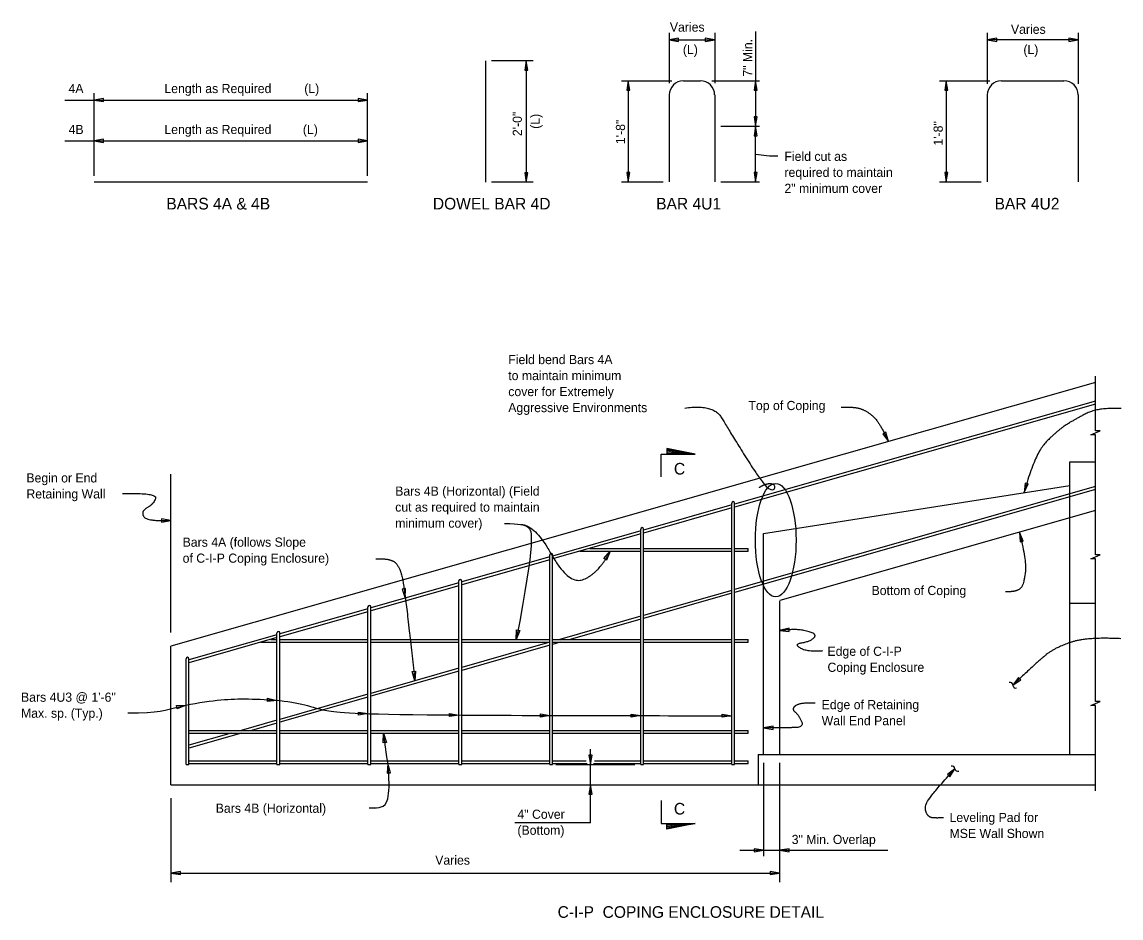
# Model space of a CAD drawing. Extents: x -15.2 to 30.6, y 0.3 to 20.9.
# Drawn here: x 0.43 to 18.56, y 0.33 to 15.1 of the extents above; entities that cross this region are included whole.
import ezdxf

# ---------------------------------------------------------------- set-up
doc = ezdxf.new("R2010")
doc.units = 0
for name, color, linetype in [('Dimension', 7, 'Continuous'), ('Rebar', 7, 'Continuous'), ('Rebar_h', 7, 'Continuous'), ('TextStructures', 7, 'Continuous'), ('WallConc', 7, 'Continuous'), ('WallConc_h', 7, 'Continuous')]:
    doc.layers.add(name, color=color, linetype=linetype)

msp = doc.modelspace()

# ---------------------------------------------------------------- linework, layer by layer
at = {"layer": 'Dimension'}
for p, q in [((11.103, 14.92), (11.103, 14.095)), ((11.854, 14.92), (11.854, 14.095)), ((12.529, 14.945), (12.529, 14.132)), ((16.349, 14.92), (16.349, 14.084)), ((17.849, 14.92), (17.849, 14.084)), ((17.849, 14.807), (16.349, 14.807)), ((8.859, 14.461), (8.171, 14.461)), ((8.746, 14.461), (8.746, 12.461)), ((10.316, 14.132), (11.144, 14.132)), ((10.429, 14.132), (10.429, 12.465)), ((11.805, 14.132), (12.594, 14.132)), ((12.529, 14.132), (12.529, 13.382)), ((15.562, 14.132), (16.394, 14.132)), ((15.674, 14.132), (15.674, 12.465)), ((1.136, 13.815), (6.128, 13.815)), ((1.619, 12.565), (1.619, 13.928)), ((6.128, 12.565), (6.128, 13.928)), ((11.954, 13.382), (12.594, 13.382)), ((12.529, 12.465), (12.529, 13.382)), ((1.136, 13.14), (6.128, 13.14)), ((8.859, 12.461), (8.171, 12.461)), ((10.316, 12.465), (11.004, 12.465)), ((11.954, 12.465), (12.594, 12.465)), ((15.562, 12.465), (16.249, 12.465)), ((11.532, 7.976), (11.063, 8.058)), ((11.063, 8.048), (11.532, 7.976)), ((11.532, 7.976), (11.063, 8.036)), ((11.063, 8.022), (11.532, 7.976)), ((11.532, 7.976), (11.063, 8.008)), ((11.063, 7.993), (11.532, 7.976)), ((2.884, 5.034), (2.884, 7.648)), ((9.805, 1.898), (9.805, 3.113)), ((9.235, 2.856), (10.536, 2.856)), ((12.661, 2.886), (12.661, 1.345)), ((12.925, 2.886), (12.925, 0.92)), ((2.885, 2.302), (2.885, 0.92)), ((9.805, 1.898), (8.559, 1.898)), ((11.063, 1.871), (11.532, 1.888)), ((11.532, 1.888), (11.063, 1.856)), ((11.063, 1.842), (11.532, 1.888)), ((11.532, 1.888), (11.063, 1.828)), ((11.063, 1.816), (11.532, 1.888)), ((11.532, 1.888), (11.063, 1.806)), ((12.271, 1.443), (14.709, 1.443)), ((2.885, 1.068), (12.925, 1.068))]:
    msp.add_line(p, q, dxfattribs=at)
for points in [[(11.102, 14.807), (11.259, 14.781), (11.259, 14.834)], [(11.854, 14.807), (11.697, 14.834), (11.697, 14.781)], [(16.349, 14.807), (16.505, 14.781), (16.505, 14.834)], [(17.849, 14.807), (17.693, 14.834), (17.693, 14.781)], [(8.746, 14.461), (8.72, 14.305), (8.773, 14.305)], [(10.428, 14.132), (10.402, 13.976), (10.455, 13.976)], [(12.529, 14.132), (12.502, 13.976), (12.555, 13.976)], [(15.674, 14.132), (15.648, 13.976), (15.701, 13.976)], [(1.619, 13.815), (1.775, 13.789), (1.775, 13.842)], [(6.128, 13.815), (5.972, 13.842), (5.972, 13.789)], [(12.529, 13.382), (12.555, 13.538), (12.502, 13.538)], [(12.529, 13.382), (12.502, 13.226), (12.555, 13.226)], [(1.619, 13.14), (1.775, 13.114), (1.775, 13.167)], [(6.128, 13.14), (5.972, 13.167), (5.972, 13.114)], [(8.746, 12.461), (8.773, 12.617), (8.72, 12.617)], [(10.429, 12.465), (10.455, 12.622), (10.402, 12.622)], [(12.529, 12.465), (12.555, 12.622), (12.502, 12.622)], [(15.674, 12.465), (15.701, 12.622), (15.648, 12.622)], [(14.721, 8.184), (14.675, 8.336), (14.628, 8.313)], [(16.958, 7.341), (17.026, 7.484), (16.975, 7.498)], [(2.884, 6.884), (2.728, 6.908), (2.729, 6.855)], [(16.881, 6.688), (16.891, 6.53), (16.942, 6.542)], [(10.026, 6.256), (10.131, 6.374), (10.071, 6.228)], [(6.75, 5.602), (6.753, 5.76), (6.7, 5.752)], [(8.637, 5.069), (8.581, 4.921), (8.585, 5.08)], [(12.925, 5.07), (13.083, 5.051), (13.08, 5.104)], [(6.918, 4.397), (6.908, 4.239), (6.865, 4.391)], [(16.772, 4.165), (16.902, 4.255), (16.865, 4.293)], [(2.976, 3.829), (3.134, 3.837), (2.988, 3.777)], [(4.48, 3.952), (4.634, 3.916), (4.477, 3.899)], [(5.978, 3.723), (6.134, 3.697), (5.978, 3.67)], [(7.478, 3.701), (7.634, 3.674), (7.478, 3.648)], [(8.978, 3.693), (9.134, 3.667), (8.978, 3.641)], [(10.478, 3.69), (10.634, 3.664), (10.478, 3.637)], [(11.978, 3.689), (12.134, 3.663), (11.978, 3.637)], [(12.661, 3.463), (12.817, 3.436), (12.817, 3.489)], [(6.388, 3.216), (6.392, 3.374), (6.44, 3.223)], [(9.805, 2.856), (9.831, 3.012), (9.778, 3.012)], [(6.462, 2.874), (6.452, 2.716), (6.505, 2.722)], [(15.817, 2.789), (15.692, 2.691), (15.732, 2.656)], [(9.805, 2.523), (9.778, 2.367), (9.831, 2.367)], [(12.661, 1.443), (12.505, 1.469), (12.505, 1.416)], [(12.925, 1.443), (13.082, 1.416), (13.082, 1.469)], [(2.885, 1.068), (3.041, 1.042), (3.041, 1.095)], [(12.925, 1.068), (12.769, 1.095), (12.769, 1.042)]]:
    msp.add_lwpolyline(points, close=True, dxfattribs=at)
for points in [[(11.103, 14.807), (11.854, 14.807)], [(18.137, 7.046), (18.137, 8.293), (18.059, 8.293), (18.137, 8.326), (18.214, 8.36), (18.137, 8.36), (18.137, 9.259)], [(10.969, 7.601), (10.969, 7.976), (11.532, 7.976), (11.063, 8.07), (11.063, 7.976)], [(18.137, 5.519), (18.137, 6.251), (18.059, 6.251), (18.137, 6.285), (18.214, 6.318), (18.137, 6.318), (18.137, 7.046)], [(18.136, 2.423), (18.136, 3.83), (18.059, 3.83), (18.136, 3.864), (18.214, 3.898), (18.136, 3.898), (18.136, 5.519)], [(10.969, 2.263), (10.969, 1.888), (11.532, 1.888), (11.063, 1.794), (11.063, 1.888)]]:
    msp.add_lwpolyline(points, dxfattribs=at)
for centre, radius, start, end in [((12.864, 14.772), 1.878, 259.7182, 270.8702), ((16.727, 4.166), 0.0447, 358.2978, 110.025), ((16.817, 4.163), 0.0447, 178.2978, 290.025), ((15.772, 2.788), 0.0447, 1.9589, 113.6861), ((15.861, 2.791), 0.0447, 181.9589, 293.6861)]:
    msp.add_arc(centre, radius, start, end, dxfattribs=at)
for points, degree in [([(11.359, 8.735), (11.83, 8.806), (12.101, 8.349), (12.68, 7.426), (12.846, 7.371), (12.846, 7.486), (12.689, 7.486), (12.586, 7.422)], 2), ([(13.942, 8.75), (14.165, 8.761), (14.38, 8.678), (14.572, 8.502), (14.721, 8.184)], 2), ([(18.556, 8.729), (18.182, 8.743), (17.808, 8.558), (17.521, 8.378), (17.129, 7.985), (16.958, 7.341)], 2), ([(2.086, 7.325), (2.652, 7.342), (2.61, 7.16), (2.384, 7.03), (2.486, 6.865), (2.884, 6.884)], 2), ([(8.385, 6.833), (8.64, 6.823), (8.78, 6.823), (8.904, 6.607), (8.581, 4.921)], 3), ([(8.659, 6.816), (8.891, 6.808), (9.45, 5.808), (9.944, 6.017), (10.131, 6.374)], 2), ([(16.881, 6.688), (17.005, 6.189), (16.949, 5.843), (16.893, 5.745), (16.76, 5.702), (16.651, 5.708)], 2), ([(6.263, 6.248), (6.525, 6.265), (6.681, 6.073), (6.748, 5.65), (6.857, 4.723), (6.908, 4.239)], 2), ([(13.633, 4.73), (13.376, 4.708), (13.156, 4.846), (13.43, 4.887), (13.552, 5.01), (13.254, 5.09), (13.009, 5.075), (12.925, 5.07)], 2), ([(18.551, 4.932), (18.004, 4.96), (17.504, 4.802), (17.21, 4.59), (16.772, 4.165)], 2), ([(2.175, 3.712), (2.686, 3.704), (2.933, 3.81), (3.638, 3.927), (4.014, 3.944), (4.562, 3.932), (5.08, 3.864), (5.376, 3.741), (6.143, 3.663), (11.598, 3.663), (12.134, 3.663)], 3), ([(13.509, 3.87), (13.266, 3.88), (13.115, 3.778), (13.238, 3.675), (13.331, 3.473), (13.047, 3.462), (12.661, 3.462)], 2), ([(6.473, 2.778), (6.472, 2.803), (6.47, 2.828), (6.392, 3.374)], 2), ([(6.154, 2.143), (6.257, 2.142), (6.362, 2.146), (6.478, 2.227), (6.49, 2.552), (6.473, 2.778)], 3), ([(15.628, 1.979), (15.442, 1.97), (15.373, 2.008), (15.316, 2.113), (15.363, 2.294), (15.817, 2.789)], 2)]:
    msp.add_open_spline(points, degree=degree, dxfattribs=at)
at = {"layer": 'Rebar'}
for p, q in [((8.071, 14.461), (8.071, 12.461)), ((16.584, 14.132), (17.615, 14.132)), ((11.104, 13.898), (11.104, 12.465)), ((11.854, 13.898), (11.854, 13.382)), ((16.349, 13.898), (16.349, 12.465)), ((17.849, 13.898), (17.849, 12.465)), ((1.619, 12.465), (6.128, 12.465)), ((18.137, 8.85), (12.181, 7.151)), ((18.137, 8.801), (12.181, 7.103)), ((18.137, 7.442), (12.181, 5.743)), ((18.137, 7.393), (12.181, 5.694)), ((12.134, 7.138), (10.681, 6.723)), ((12.134, 7.089), (10.681, 6.675)), ((12.134, 2.856), (12.134, 7.169)), ((12.181, 2.856), (12.181, 7.169)), ((10.634, 6.71), (9.181, 6.296)), ((10.634, 2.856), (10.634, 6.741)), ((10.681, 2.856), (10.681, 6.741)), ((10.634, 6.661), (9.181, 6.247)), ((9.628, 6.374), (10.634, 6.374)), ((9.793, 6.421), (10.634, 6.421)), ((10.681, 6.421), (12.134, 6.421)), ((10.681, 6.374), (12.134, 6.374)), ((12.181, 6.421), (12.404, 6.421)), ((12.181, 6.374), (12.404, 6.374)), ((12.404, 6.374), (12.404, 6.421)), ((9.134, 6.282), (7.681, 5.868)), ((9.134, 6.233), (7.681, 5.819)), ((9.134, 2.856), (9.134, 6.313)), ((9.181, 2.856), (9.181, 6.313)), ((7.634, 5.854), (6.181, 5.44)), ((7.634, 5.806), (6.181, 5.391)), ((7.634, 2.856), (7.634, 5.885)), ((7.681, 2.856), (7.681, 5.885)), ((12.134, 5.73), (10.681, 5.315)), ((12.134, 5.681), (10.681, 5.266)), ((6.134, 2.856), (6.134, 5.458)), ((6.181, 2.856), (6.181, 5.458)), ((6.134, 5.427), (4.681, 5.012)), ((6.134, 5.378), (4.681, 4.963)), ((10.634, 5.302), (9.301, 4.921)), ((10.634, 5.253), (9.472, 4.921)), ((4.634, 4.999), (3.181, 4.584)), ((4.634, 4.95), (3.181, 4.535)), ((4.534, 4.921), (4.634, 4.921)), ((4.634, 2.856), (4.634, 5.03)), ((4.681, 2.856), (4.681, 5.03)), ((4.681, 4.921), (6.134, 4.921)), ((6.181, 4.921), (7.634, 4.921)), ((7.681, 4.921), (9.134, 4.921)), ((9.181, 4.921), (10.634, 4.921)), ((10.681, 4.921), (12.134, 4.921)), ((12.181, 4.921), (12.404, 4.921)), ((12.404, 4.874), (12.404, 4.921)), ((4.369, 4.874), (4.634, 4.874)), ((4.681, 4.874), (6.134, 4.874)), ((6.181, 4.874), (7.634, 4.874)), ((7.681, 4.874), (9.134, 4.874)), ((9.134, 4.874), (7.681, 4.459)), ((9.134, 4.825), (7.681, 4.41)), ((9.181, 4.874), (10.634, 4.874)), ((9.307, 4.874), (9.181, 4.838)), ((10.681, 4.874), (12.134, 4.874)), ((12.181, 4.874), (12.404, 4.874)), ((3.134, 2.856), (3.134, 4.602)), ((3.181, 2.856), (3.181, 4.602)), ((7.634, 4.446), (6.181, 4.031)), ((7.634, 4.397), (6.181, 3.983)), ((6.134, 4.018), (4.681, 3.603)), ((6.134, 3.969), (4.681, 3.555)), ((4.634, 3.59), (4.043, 3.421)), ((4.634, 3.541), (4.214, 3.421)), ((3.181, 3.421), (4.634, 3.421)), ((3.181, 3.374), (4.634, 3.374)), ((4.049, 3.374), (3.181, 3.127)), ((3.878, 3.374), (3.181, 3.175)), ((4.681, 3.421), (6.134, 3.421)), ((4.681, 3.374), (6.134, 3.374)), ((6.181, 3.421), (7.634, 3.421)), ((6.181, 3.374), (7.634, 3.374)), ((7.681, 3.421), (9.134, 3.421)), ((7.681, 3.374), (9.134, 3.374)), ((9.181, 3.421), (10.634, 3.421)), ((9.181, 3.374), (10.634, 3.374)), ((10.681, 3.421), (12.134, 3.421)), ((10.681, 3.374), (12.134, 3.374)), ((12.181, 3.421), (12.404, 3.421)), ((12.181, 3.374), (12.404, 3.374)), ((12.404, 3.374), (12.404, 3.421)), ((3.181, 2.921), (4.634, 2.921)), ((4.681, 2.921), (6.134, 2.921)), ((6.181, 2.921), (7.634, 2.921)), ((7.681, 2.921), (9.134, 2.921)), ((9.181, 2.921), (9.736, 2.921)), ((9.87, 2.921), (10.634, 2.921)), ((10.681, 2.921), (12.134, 2.921)), ((12.181, 2.921), (12.404, 2.921)), ((12.404, 2.874), (12.404, 2.921)), ((3.134, 2.856), (3.181, 2.856)), ((3.181, 2.874), (4.634, 2.874)), ((4.634, 2.856), (4.681, 2.856)), ((4.681, 2.874), (6.134, 2.874)), ((6.134, 2.856), (6.181, 2.856)), ((6.181, 2.874), (7.634, 2.874)), ((7.634, 2.856), (7.681, 2.856)), ((7.681, 2.874), (9.134, 2.874)), ((9.134, 2.856), (9.181, 2.856)), ((9.181, 2.874), (9.752, 2.874)), ((9.852, 2.874), (10.634, 2.874)), ((10.634, 2.856), (10.681, 2.856)), ((10.681, 2.874), (12.134, 2.874)), ((12.134, 2.856), (12.181, 2.856)), ((12.181, 2.874), (12.404, 2.874))]:
    msp.add_line(p, q, dxfattribs=at)
msp.add_lwpolyline([(11.338, 14.132), (11.619, 14.132)], dxfattribs=at)
for centre, radius, start, end in [((11.338, 13.898), 0.234, 90, 180), ((11.619, 13.898), 0.234, 0, 90), ((16.584, 13.898), 0.234, 90, 180), ((17.615, 13.898), 0.234, 0, 90), ((12.158, 7.169), 0.0234, 0, 180), ((10.658, 6.741), 0.0234, 0, 180), ((9.158, 6.313), 0.0234, 0, 180), ((7.658, 5.885), 0.0234, 0, 180), ((6.158, 5.458), 0.0234, 0, 180), ((4.658, 5.03), 0.0234, 0, 180), ((3.158, 4.602), 0.0234, 0, 180)]:
    msp.add_arc(centre, radius, start, end, dxfattribs=at)
at = {"layer": 'Rebar_h'}
msp.add_line((11.854, 13.382), (11.854, 12.465), dxfattribs=at)
at = {"layer": 'TextStructures'}
msp.add_ellipse((12.86, 6.558), major_axis=(0, 0.935), ratio=0.359387, dxfattribs=at)
at = {"layer": 'WallConc'}
for p, q in [((18.136, 9.159), (2.884, 4.808)), ((18.136, 7.046), (12.926, 5.56)), ((17.709, 3.023), (17.709, 6.924)), ((12.925, 5.559), (12.925, 3.023)), ((17.709, 5.519), (18.137, 5.519)), ((2.884, 2.523), (2.884, 4.808)), ((12.571, 3.023), (18.136, 3.023)), ((12.571, 3.022), (12.571, 2.523)), ((2.884, 2.523), (18.136, 2.523))]:
    msp.add_line(p, q, dxfattribs=at)
for centre, start, end in [((12.926, 5.559), 105.9205, 180), ((17.709, 4.272), 270, 0), ((2.885, 2.523), 180, 270)]:
    msp.add_arc(centre, 0.000625, start, end, dxfattribs=at)
at = {"layer": 'WallConc_h'}
for p, q in [((17.709, 7.851), (18.136, 7.851)), ((17.709, 6.924), (17.709, 7.851)), ((12.661, 6.666), (17.709, 7.459)), ((12.661, 3.023), (12.661, 6.666))]:
    msp.add_line(p, q, dxfattribs=at)
msp.add_arc((16.941, 7.338), 0.000625, 0, 98.9205, dxfattribs=at)

# ---------------------------------------------------------------- texts
at = {"layer": 'Dimension'}
for s, p in [('7" Min.', (12.473, 14.2)), ('1\'-8"', (10.375, 13.088)), ('1\'-8"', (15.615, 13.063))]:
    msp.add_text(s, height=0.1512, rotation=90, dxfattribs=at).set_placement(p)
for s, p in [('Field cut as', (13.004, 12.811)), ('required to maintain', (13.004, 12.547)), ('2" minimum cover', (13.004, 12.283)), ('Field bend Bars 4A', (8.449, 9.46)), ('to maintain minimum', (8.449, 9.196)), ('cover for Extremely', (8.449, 8.932)), ('Aggressive Environments', (8.449, 8.668)), ('Begin or End ', (0.501, 7.509)), ('Bars 4B (Horizontal) (Field', (6.584, 7.291)), ('Retaining Wall', (0.501, 7.245)), ('cut as required to maintain', (6.584, 7.027)), ('minimum cover)', (6.584, 6.763)), ('Bars 4A (follows Slope', (3.078, 6.449)), ('of C-I-P Coping Enclosure)', (3.078, 6.185)), ('Edge of C-I-P', (13.714, 4.65)), ('Coping Enclosure', (13.714, 4.386)), ('Bars 4U3 @ 1\'-6" ', (0.412, 3.893)), ('Edge of Retaining', (13.618, 3.77)), ('Max. sp. (Typ.)', (0.412, 3.629)), ('Wall End Panel', (13.618, 3.506)), ('4" Cover', (8.6, 1.963)), ('(Bottom)', (8.6, 1.699))]:
    msp.add_text(s, height=0.1512, dxfattribs=at).set_placement(p)
at = {"layer": 'TextStructures'}
for s, height, p in [('Varies', 0.1512, (11.114, 14.942)), ('Varies', 0.1512, (16.74, 14.906)), ('(L)', 0.1512, (11.329, 14.572)), ('(L)', 0.1512, (16.945, 14.572)), ('4A', 0.1512, (1.196, 13.929)), ('Length as Required', 0.1512, (2.777, 13.929)), ('(L)', 0.1512, (5.084, 13.929)), ('4B', 0.1512, (1.197, 13.254)), ('Length as Required', 0.1512, (2.777, 13.254)), ('(L)', 0.1512, (5.061, 13.254)), ('BARS 4A & 4B', 0.192, (2.809, 12.01)), ('DOWEL BAR 4D', 0.192, (7.205, 12.01)), ('BAR 4U1', 0.192, (10.888, 12.01)), ('BAR 4U2', 0.192, (16.47, 12.01)), ('Top of Coping', 0.1512, (12.41, 8.702)), ('C', 0.192, (11.181, 7.639)), ('Bottom of Coping', 0.1512, (14.441, 5.652)), ('Bars 4B (Horizontal)', 0.1512, (3.624, 2.062)), ('C', 0.192, (11.181, 2.033)), ('Leveling Pad for', 0.1512, (15.727, 1.91)), ('3" Min. Overlap', 0.1512, (13.124, 1.547)), ('MSE Wall Shown', 0.1512, (15.727, 1.646)), ('Varies', 0.1512, (7.244, 1.206)), ('C-I-P  COPING ENCLOSURE DETAIL', 0.192, (9.263, 0.33))]:
    msp.add_text(s, height=height, dxfattribs=at).set_placement(p)
for s, p in [('2\'-0"', (8.673, 13.22)), ('(L)', (8.969, 13.34))]:
    msp.add_text(s, height=0.1512, rotation=90, dxfattribs=at).set_placement(p)

doc.saveas('drawing.dxf')
